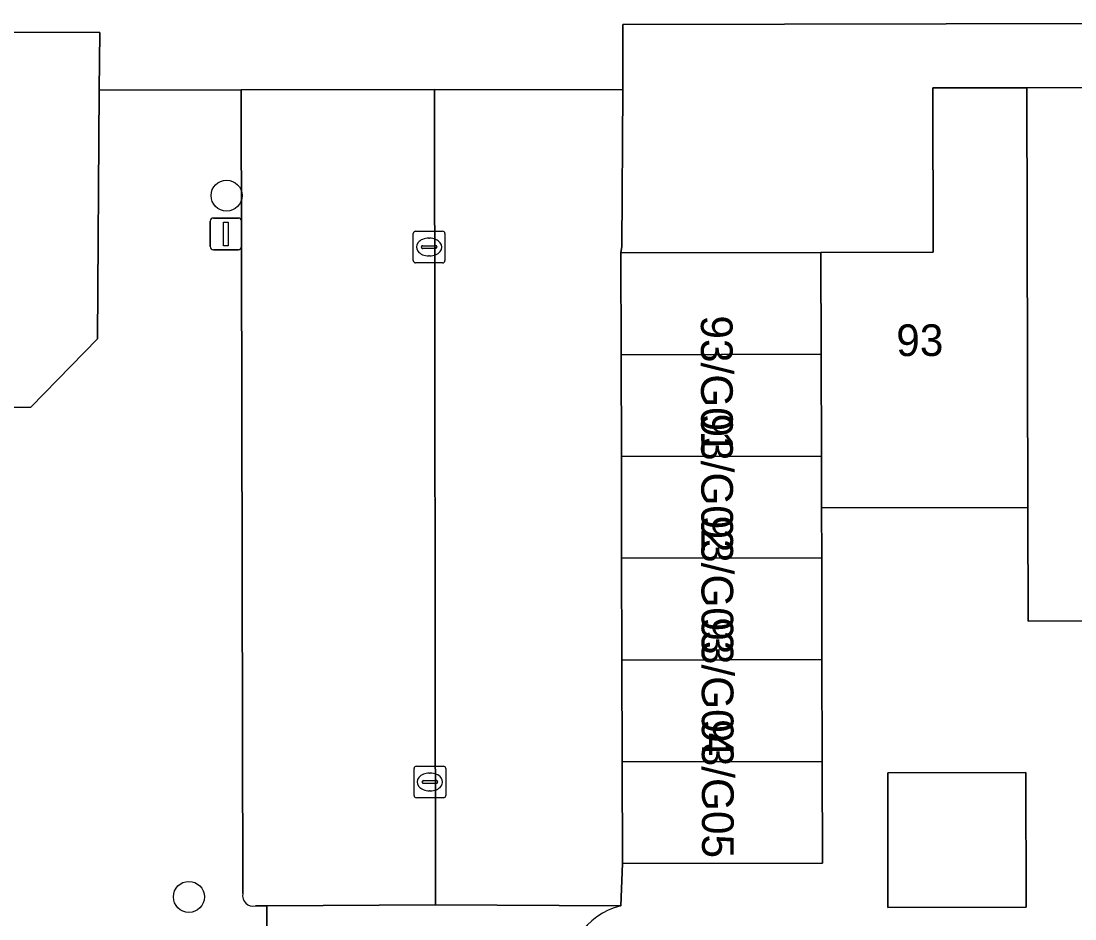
# Model space of a CAD drawing. Extents: x 160732 to 162107, y 387428 to 388479.
# Drawn here: x 161055.26 to 161088.54, y 388296.86 to 388325.22 of the extents above; entities that cross this region are included whole.
import ezdxf

# ---------------------------------------------------------------- set-up
doc = ezdxf.new("R2010")
doc.units = 0
for name, color, linetype in [('IMGEO_Boom', 7, 'Continuous'), ('IMGEO_Erf', 7, 'Continuous'), ('IMGEO_Groenvoorziening', 7, 'Continuous'), ('IMGEO_Kolk', 7, 'Continuous'), ('IMGEO_Lichtmast', 7, 'Continuous'), ('IMGEO_Pand', 7, 'Continuous'), ('IMGEO_Pand_nummerreeks', 7, 'Continuous'), ('IMGEO_Parkeervlak_open', 7, 'Continuous'), ('IMGEO_Rijbaan_lokaal_open', 7, 'Continuous'), ('IMGEO_Voetpad_open', 7, 'Continuous')]:
    doc.layers.add(name, color=color, linetype=linetype)

msp = doc.modelspace()

# ---------------------------------------------------------------- linework, layer by layer
at = {"layer": 'IMGEO_Boom'}
for centre in [(161061.748, 388319.703), (161060.559, 388297.557)]:
    msp.add_circle(centre, 0.489, dxfattribs=at)
at = {"layer": 'IMGEO_Erf'}
for points in [[(161120.205, 388325.197), (161074.263, 388325.112), (161074.262, 388323.039), (161074.234, 388318.1), (161074.204, 388317.894), (161080.522, 388317.909), (161084.063, 388317.917), (161084.05, 388323.104), (161087.02, 388323.111), (161089.989, 388323.118)], [(161093.403, 388306.278), (161087.062, 388306.263), (161087.053, 388309.859), (161080.542, 388309.844), (161080.546, 388308.266), (161080.554, 388305.051), (161080.561, 388301.837), (161080.569, 388298.622), (161074.249, 388298.608), (161074.201, 388297.277)]]:
    msp.add_lwpolyline(points, dxfattribs=at)
msp.add_lwpolyline([(161082.639, 388297.228), (161082.629, 388301.478), (161086.99, 388301.487), (161086.999, 388297.237)], close=True, dxfattribs=at)
msp.add_arc((161074.689, 388295.202), 2.131, 103.2344, 191.5895, dxfattribs=at)
at = {"layer": 'IMGEO_Groenvoorziening'}
for points in [[(161062.208, 388323.039), (161057.725, 388323.029), (161057.668, 388315.185), (161055.566, 388313.019), (161051.653, 388312.996), (161051.662, 388296.134), (161050.975, 388296.134), (161050.982, 388293.719), (161063.025, 388293.698), (161063.025, 388297.273), (161062.664, 388297.271)], [(161062.26, 388297.666), (161062.208, 388323.039)]]:
    msp.add_lwpolyline(points, dxfattribs=at)
msp.add_arc((161062.595, 388297.605), 0.341, 169.6267, 281.664, dxfattribs=at)
at = {"layer": 'IMGEO_Kolk'}
for p, q in [((161067.646, 388317.653), (161067.646, 388318.505)), ((161067.721, 388318.579), (161068.573, 388318.579)), ((161068.647, 388318.505), (161068.647, 388317.653)), ((161067.905, 388318.073), (161067.905, 388318.085)), ((161067.948, 388318.122), (161068.346, 388318.122)), ((161068.134, 388318.359), (161068.159, 388318.359)), ((161068.389, 388318.085), (161068.389, 388318.073)), ((161068.343, 388318.036), (161067.945, 388318.036)), ((161068.157, 388317.799), (161068.132, 388317.799)), ((161068.573, 388317.579), (161067.721, 388317.579)), ((161067.67, 388300.761), (161067.67, 388301.613)), ((161067.745, 388301.687), (161068.597, 388301.687)), ((161068.158, 388301.467), (161068.183, 388301.467)), ((161068.671, 388301.613), (161068.671, 388300.761)), ((161067.929, 388301.181), (161067.929, 388301.193)), ((161068.367, 388301.144), (161067.969, 388301.144)), ((161067.972, 388301.23), (161068.37, 388301.23)), ((161068.413, 388301.193), (161068.413, 388301.181)), ((161068.181, 388300.907), (161068.156, 388300.907)), ((161068.597, 388300.687), (161067.745, 388300.687))]:
    msp.add_line(p, q, dxfattribs=at)
for points in [[(161067.646, 388317.653), (161067.646, 388318.505)], [(161067.721, 388318.579), (161068.573, 388318.579)], [(161068.647, 388318.505), (161068.647, 388317.653)], [(161068.573, 388317.579), (161067.721, 388317.579)], [(161067.67, 388300.761), (161067.67, 388301.613)], [(161067.745, 388301.687), (161068.597, 388301.687)], [(161068.671, 388301.613), (161068.671, 388300.761)], [(161068.597, 388300.687), (161067.745, 388300.687)]]:
    msp.add_lwpolyline(points, dxfattribs=at)
for centre, radius, start, end in [((161067.723, 388318.503), 0.0765, 91.552, 178.448), ((161067.723, 388318.503), 0.0765, 91.552, 178.448), ((161068.571, 388318.503), 0.0765, 1.552, 88.448), ((161068.571, 388318.503), 0.0765, 1.552, 88.448), ((161067.945, 388318.082), 0.0403, 85.8775, 175.7526), ((161068.35, 388318.084), 0.0386, 1.7309, 96.639), ((161067.942, 388318.072), 0.0366, 178.938, 274.7102), ((161068.346, 388318.079), 0.043, 264.8664, 352.4533), ((161067.723, 388317.655), 0.0765, 181.552, 268.448), ((161067.723, 388317.655), 0.0765, 181.552, 268.448), ((161068.571, 388317.655), 0.0765, 271.552, 358.448), ((161068.571, 388317.655), 0.0765, 271.552, 358.448), ((161067.747, 388301.611), 0.0765, 91.552, 178.448), ((161067.747, 388301.611), 0.0765, 91.552, 178.448), ((161068.595, 388301.611), 0.0765, 1.552, 88.448), ((161068.595, 388301.611), 0.0765, 1.552, 88.448), ((161067.969, 388301.19), 0.0403, 85.8775, 175.7526), ((161067.966, 388301.18), 0.0366, 178.938, 274.7102), ((161068.37, 388301.187), 0.043, 264.8664, 352.4533), ((161068.374, 388301.192), 0.0386, 1.7309, 96.639), ((161067.747, 388300.763), 0.0765, 181.552, 268.448), ((161067.747, 388300.763), 0.0765, 181.552, 268.448), ((161068.595, 388300.763), 0.0765, 271.552, 358.448), ((161068.595, 388300.763), 0.0765, 271.552, 358.448)]:
    msp.add_arc(centre, radius, start, end, dxfattribs=at)
for centre, major_axis, ratio, start_param, end_param in [((161068.133, 388318.079), (-0.387, 0.002), 0.722429, 4.712389, 7.853982), ((161068.158, 388318.079), (-0.39, 0.002), 0.717154, 1.570796, 4.712389), ((161068.157, 388301.187), (-0.387, 0.002), 0.722429, 4.712389, 7.853982), ((161068.182, 388301.187), (-0.39, 0.002), 0.717154, 1.570796, 4.712389)]:
    msp.add_ellipse(centre, major_axis=major_axis, ratio=ratio, start_param=start_param, end_param=end_param, dxfattribs=at)
at = {"layer": 'IMGEO_Lichtmast'}
for p, q in [((161061.231, 388318.095), (161061.231, 388318.895)), ((161061.231, 388318.895), (161061.231, 388318.095)), ((161061.331, 388318.995), (161062.121, 388318.995)), ((161062.121, 388318.995), (161061.331, 388318.995)), ((161062.221, 388318.895), (161062.221, 388318.095)), ((161062.221, 388318.095), (161062.221, 388318.895)), ((161062.121, 388317.995), (161061.331, 388317.995)), ((161061.331, 388317.995), (161062.121, 388317.995))]:
    msp.add_line(p, q, dxfattribs=at)
msp.add_lwpolyline([(161061.651, 388318.87), (161061.801, 388318.87), (161061.801, 388318.12), (161061.651, 388318.12), (161061.651, 388318.87)], dxfattribs=at)
for centre, start, end in [((161061.331, 388318.895), 90, 180), ((161061.331, 388318.895), 90, 180), ((161062.121, 388318.895), 0, 90), ((161062.121, 388318.895), 360, 90), ((161061.331, 388318.095), 180, 270), ((161061.331, 388318.095), 180, 270), ((161062.121, 388318.095), 270, 0), ((161062.121, 388318.095), 270, 0)]:
    msp.add_arc(centre, 0.1, start, end, dxfattribs=at)
at = {"layer": 'IMGEO_Pand'}
for points in [[(161080.522, 388317.909), (161080.53, 388314.694), (161080.538, 388311.48), (161080.542, 388309.844), (161087.053, 388309.859), (161087.02, 388323.111), (161084.05, 388323.104), (161084.063, 388317.917)], [(161093.37, 388317.959), (161090.002, 388317.952), (161089.989, 388323.118), (161087.02, 388323.111), (161087.053, 388309.859), (161087.062, 388306.263), (161093.403, 388306.278), (161093.388, 388309.874)], [(161074.211, 388314.68), (161080.53, 388314.694), (161080.522, 388317.909), (161074.204, 388317.894)], [(161074.219, 388311.465), (161080.538, 388311.48), (161080.53, 388314.694), (161074.211, 388314.68)], [(161080.542, 388309.844), (161080.538, 388311.48), (161074.219, 388311.465), (161074.226, 388308.251), (161080.546, 388308.266)], [(161080.546, 388308.266), (161074.226, 388308.251), (161074.234, 388305.037), (161080.554, 388305.051)], [(161080.554, 388305.051), (161074.234, 388305.037), (161074.241, 388301.822), (161080.561, 388301.837)], [(161080.561, 388301.837), (161074.241, 388301.822), (161074.249, 388298.608), (161080.569, 388298.622)], [(161082.629, 388301.478), (161082.639, 388297.228), (161086.999, 388297.237), (161086.99, 388301.487)]]:
    msp.add_lwpolyline(points, close=True, dxfattribs=at)
at = {"layer": 'IMGEO_Parkeervlak_open'}
msp.add_lwpolyline([(161062.664, 388297.271), (161063.025, 388297.273), (161068.35, 388297.308), (161068.317, 388323.054), (161062.208, 388323.039), (161062.26, 388297.666)], dxfattribs=at)
msp.add_arc((161062.595, 388297.605), 0.341, 169.6267, 281.664, dxfattribs=at)
at = {"layer": 'IMGEO_Rijbaan_lokaal_open'}
msp.add_lwpolyline([(161074.234, 388318.1), (161074.262, 388323.039), (161068.317, 388323.054), (161068.35, 388297.308), (161074.201, 388297.277), (161074.249, 388298.608), (161074.241, 388301.822), (161074.234, 388305.037), (161074.226, 388308.251), (161074.219, 388311.465), (161074.211, 388314.68), (161074.204, 388317.894)], close=True, dxfattribs=at)
at = {"layer": 'IMGEO_Voetpad_open'}
for points in [[(161051.873, 388324.861), (161057.751, 388324.859), (161057.725, 388323.029), (161062.208, 388323.039), (161068.317, 388323.054), (161074.262, 388323.039), (161074.263, 388325.112), (161120.205, 388325.197), (161120.757, 388325.168), (161125.39, 388325.215), (161126.249, 388325.162), (161129.977, 388325.147), (161137.267, 388325.211), (161151.542, 388325.215)], [(161053.009, 388313.814), (161051.653, 388313.882), (161051.653, 388312.996), (161055.566, 388313.019), (161057.668, 388315.185), (161057.725, 388323.029), (161057.751, 388324.859), (161051.873, 388324.861), (161050.794, 388324.883), (161049.306, 388324.884), (161049.238, 388321.863)], [(161074.201, 388297.277), (161068.35, 388297.308), (161063.025, 388297.273), (161063.025, 388293.698), (161063.025, 388292.189), (161065.055, 388292.169), (161065.052, 388293.176), (161069.88, 388293.228), (161074.95, 388276.839), (161075.343, 388275.567), (161084.788, 388245.034), (161087.901, 388245.034), (161072.601, 388294.774)]]:
    msp.add_lwpolyline(points, dxfattribs=at)
msp.add_arc((161074.689, 388295.202), 2.131, 103.2344, 191.5895, dxfattribs=at)

# ---------------------------------------------------------------- texts
at = {"layer": 'IMGEO_Pand_nummerreeks'}
for s, rotation, p in [('93/G01', 270.1337, (161076.729, 388315.919)), ('93', 0.1677, (161082.902, 388314.636)), ('93/G02', 270.1337, (161076.736, 388312.821)), ('93/G03', 270.1337, (161076.743, 388309.6)), ('93/G04', 270.1337, (161076.751, 388306.386)), ('93/G05', 270.1337, (161076.758, 388303.171))]:
    msp.add_text(s, height=1, rotation=rotation, dxfattribs=at).set_placement(p)

doc.saveas('drawing.dxf')
